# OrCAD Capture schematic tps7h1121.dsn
size Custom
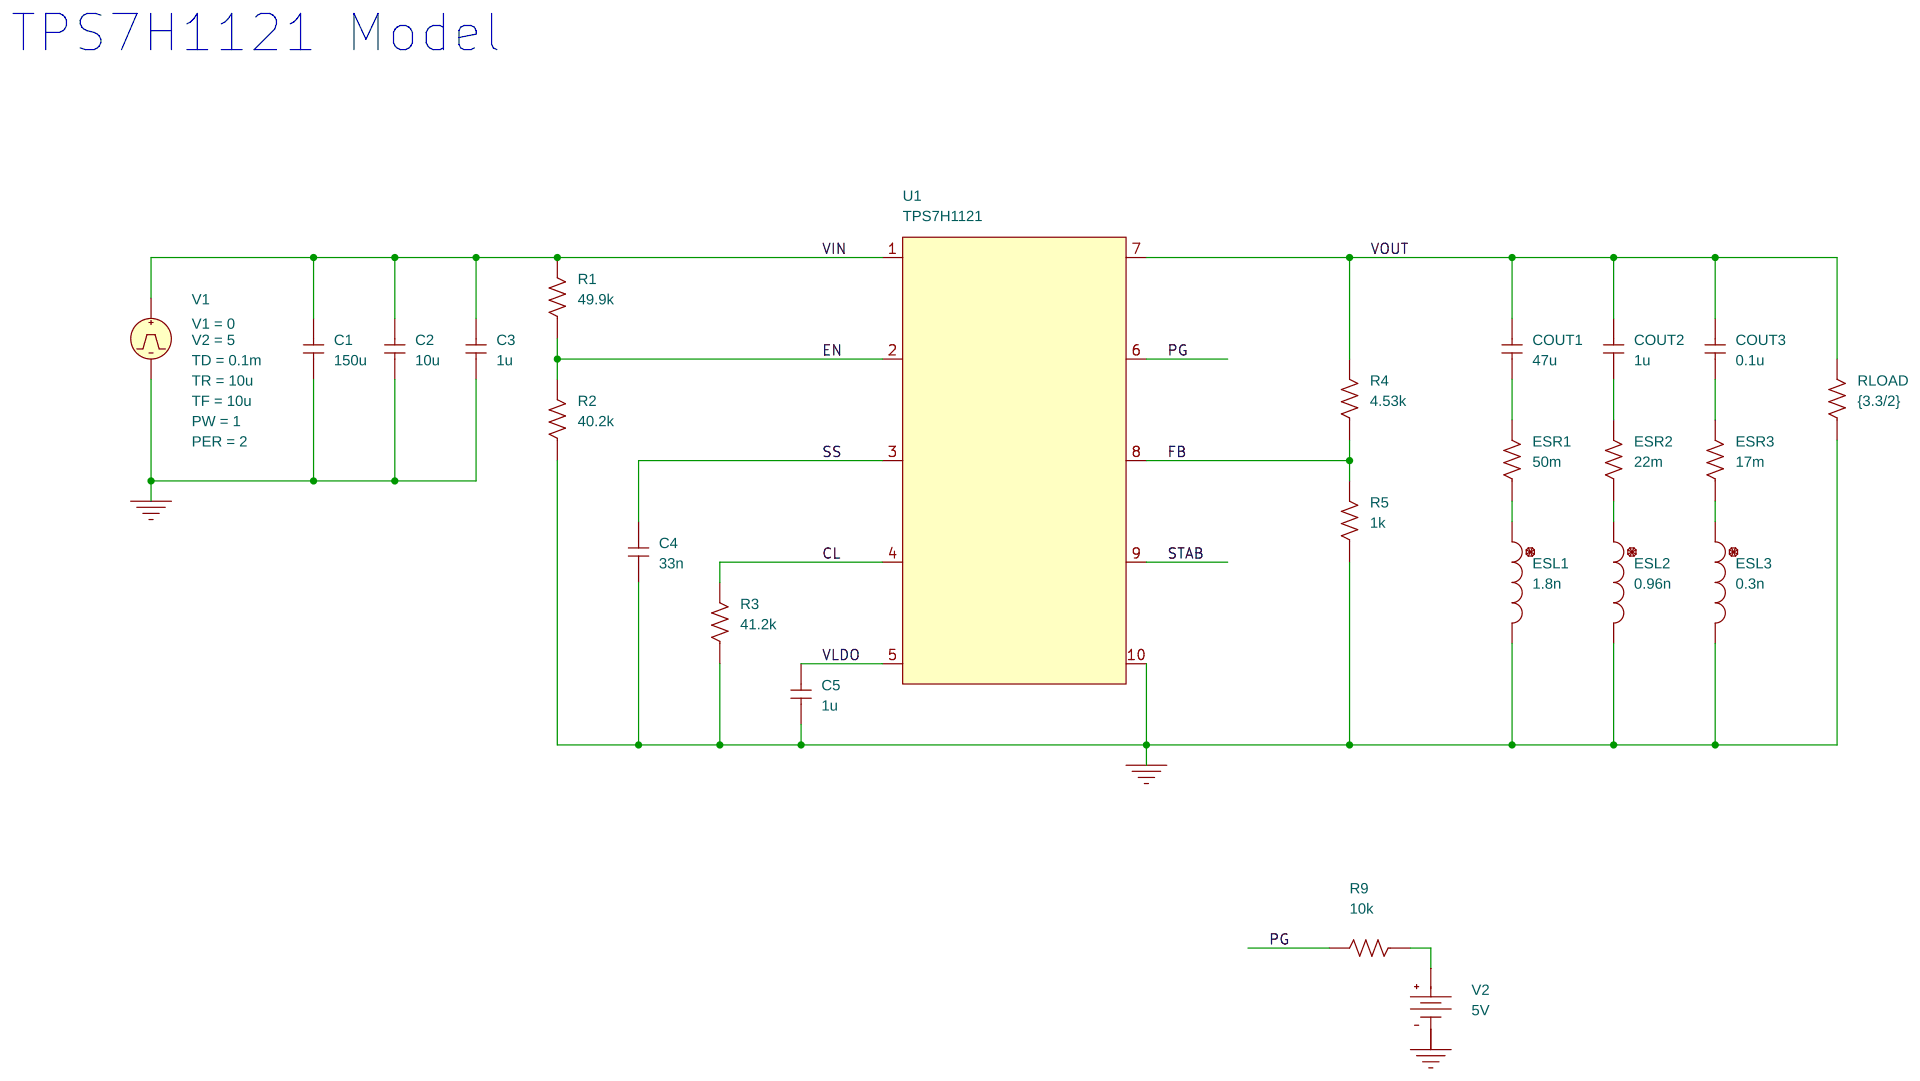
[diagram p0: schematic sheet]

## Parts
C1  150u  [cap196]
C2  10u  [cap196]
C3  1u  [cap196]
C4  33n  [cap196]
C5  1u  [cap196]
COUT1  47u  [cap196]
COUT2  1u  [cap196]
COUT3  0.1u  [cap196]
ESL1  1.8n  [DISC350x175LS200x100034]
ESL2  0.96n  [DISC350x175LS200x100034]
ESL3  0.3n  [DISC350x175LS200x100034]
ESR1  50m  [AXRC05]
ESR2  22m  [AXRC05]
ESR3  17m  [AXRC05]
R1  49.9k  [AXRC05]
R2  40.2k  [AXRC05]
R3  41.2k  [AXRC05]
R4  4.53k  [AXRC05]
R5  1k  [AXRC05]
R9  10k  [AXRC05]
RLOAD  {3.3/2}  [AXRC05]
U1  TPS7H1121
V1  VPULSE
V2  VDC

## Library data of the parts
C1-C5 COUT1-COUT3 = C
ESL1-ESL3 = L
ESR1-ESR3 R1-R5 R9 RLOAD = R
U1 = TPS7H1121
V1 = VPULSE: PER: 2; PW: 1; TD: 0.1m; TF: 10u; TR: 10u; V1: 0; V2: 5
V2 = VDC: DC: 5V

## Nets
VIN: C1.1 C2.1 C3.1 R1.2 U1.1(VIN) V1.1(+)
0: C1.2 C2.2 C3.2 C4.2 C5.2 ESL1.2 ESL2.2 ESL3.2 R2.1 R3.1 R5.1 RLOAD.1 U1.10(GND) V1.2(-) V2.1(-)
CL: R3.2 U1.4(RCL)
EN: R1.1 R2.2 U1.2(EN)
FB: R4.1 R5.2 U1.8(FB)
PG: R9.2 U1.6(PG)
SS: C4.1 U1.3(SS)
STAB: U1.9(STAB)
VLDO: C5.1 U1.5(VLDO)
VOUT: COUT1.1 COUT2.1 COUT3.1 R4.2 RLOAD.2 U1.7(VOUT)
N16639520: COUT1.2 ESR1.2
N16639526: COUT2.2 ESR2.2
N16639530: COUT3.2 ESR3.2
N16639914: R9.1 V2.0(+)
N16642175: ESL1.1 ESR1.1
N16642951: ESL2.1 ESR2.1
N16643030: ESL3.1 ESR3.1

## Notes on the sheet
- TPS7H1121 Model
